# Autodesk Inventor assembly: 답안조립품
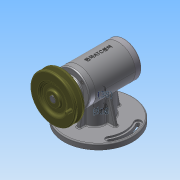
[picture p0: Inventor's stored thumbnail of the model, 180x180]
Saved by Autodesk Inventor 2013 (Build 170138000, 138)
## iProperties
Created: 2017-06
Part Number: 답안조립품
Document SubType Name: Assembly
Designer: Administrator
Author: Administrator
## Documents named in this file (15)
- C:\Users\Administrator\Desktop\370608V1024\답안조립품.iam
- C:\Users\Administrator\Desktop\370608V1024\V-벨트풀리.ipt
- C:\Users\Administrator\Desktop\370608V1024\뒤커버.ipt
- C:\Users\Administrator\Desktop\370608V1024\멈춤나사 M3x8.ipt
- C:\Users\Administrator\Desktop\370608V1024\베어링 6201.ipt
- C:\Users\Administrator\Desktop\370608V1024\베어링 6202.ipt
- C:\Users\Administrator\Desktop\370608V1024\본체.ipt
- C:\Users\Administrator\Desktop\370608V1024\본체커버.ipt
- C:\Users\Administrator\Desktop\370608V1024\볼트 M3x0.5x8.ipt
- C:\Users\Administrator\Desktop\370608V1024\슬라이드.ipt
- C:\Users\Administrator\Desktop\370608V1024\앞커버.ipt
- C:\Users\Administrator\Desktop\370608V1024\오일실 12 22 7.ipt
- C:\Users\Administrator\Desktop\370608V1024\키 4 x 4 x 18.ipt
- C:\Users\Administrator\Desktop\370608V1024\편심축.ipt
- C:\Users\Administrator\Desktop\370608V1024\가변스프링.ipt
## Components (2 placed, 2 different names)
1. V-벨트풀리:1
2. 가변스프링:1
